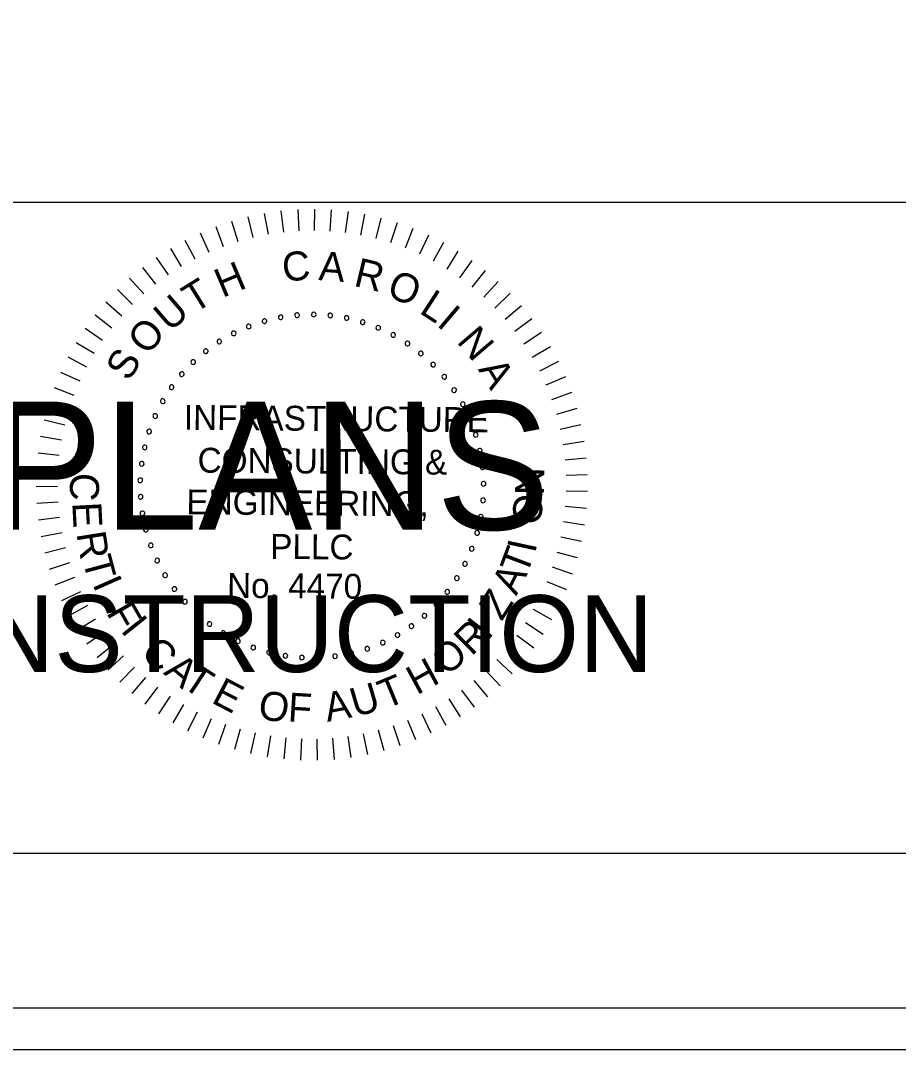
# Model space of a CAD drawing. Extents: x 967 to 1326, y 964 to 3144.
# Drawn here: x 1189.3 to 1212.88, y 2923.72 to 2951.36 of the extents above; entities that cross this region are included whole.
import ezdxf

# ---------------------------------------------------------------- set-up
doc = ezdxf.new("R2010")
doc.units = 0
for name, color, linetype in [('RD_SHT_Bndy', 7, 'Continuous'), ('RD_SHT_IplotShp', 7, 'Continuous'), ('RD_SHT_Misc1', 7, 'Continuous'), ('RD_SHT_Misc2', 7, 'Continuous'), ('RD_Sketch1', 7, 'Continuous')]:
    doc.layers.add(name, color=color, linetype=linetype)

msp = doc.modelspace()

# ---------------------------------------------------------------- linework, layer by layer
at = {"layer": 'RD_SHT_Bndy'}
for p, q in [((996.114, 2946.486), (1323.886, 2946.486)), ((1323.886, 2928.983), (996.114, 2928.983))]:
    msp.add_line(p, q, dxfattribs=at)
at = {"layer": 'RD_SHT_IplotShp'}
for points in [[(967.409, 2923.72), (1326.285, 2923.72), (1326.285, 3143.72), (967.409, 3143.72)], [(988.525, 2924.84), (1326.285, 2924.84), (1326.285, 3142.6), (988.525, 3142.6)]]:
    msp.add_lwpolyline(points, close=True, dxfattribs=at)
at = {"layer": 'RD_SHT_Misc1'}
for p, q in [((1195.846, 2946.181), (1195.945, 2945.62)), ((1196.292, 2946.245), (1196.357, 2945.68)), ((1196.742, 2946.282), (1196.772, 2945.714)), ((1197.194, 2946.292), (1197.189, 2945.723)), ((1197.645, 2946.274), (1197.606, 2945.706)), ((1198.094, 2946.228), (1198.02, 2945.664)), ((1198.54, 2946.156), (1198.432, 2945.596)), ((1194.968, 2945.971), (1195.134, 2945.427)), ((1195.403, 2946.09), (1195.536, 2945.536)), ((1198.98, 2946.056), (1198.838, 2945.504)), ((1199.414, 2945.929), (1199.238, 2945.387)), ((1194.122, 2945.656), (1194.353, 2945.136)), ((1194.54, 2945.827), (1194.739, 2945.293)), ((1199.839, 2945.777), (1199.63, 2945.246)), ((1200.253, 2945.598), (1200.013, 2945.082)), ((1193.715, 2945.461), (1193.978, 2944.956)), ((1200.656, 2945.395), (1200.385, 2944.894)), ((1193.321, 2945.241), (1193.614, 2944.752)), ((1201.047, 2945.167), (1200.745, 2944.684)), ((1192.94, 2944.997), (1193.263, 2944.528)), ((1201.422, 2944.917), (1201.092, 2944.453)), ((1192.576, 2944.731), (1192.926, 2944.282)), ((1201.781, 2944.643), (1201.424, 2944.2)), ((1192.228, 2944.443), (1192.605, 2944.016)), ((1202.124, 2944.349), (1201.739, 2943.928)), ((1191.899, 2944.134), (1192.301, 2943.731)), ((1202.447, 2944.034), (1202.038, 2943.638)), ((1191.589, 2943.805), (1192.015, 2943.428)), ((1202.751, 2943.7), (1202.318, 2943.329)), ((1191.299, 2943.459), (1191.748, 2943.108)), ((1191.032, 2943.095), (1191.501, 2942.772)), ((1203.034, 2943.348), (1202.579, 2943.004)), ((1203.294, 2942.979), (1202.82, 2942.664)), ((1190.787, 2942.716), (1191.274, 2942.422)), ((1203.532, 2942.595), (1203.04, 2942.31)), ((1190.565, 2942.323), (1191.07, 2942.059)), ((1203.746, 2942.198), (1203.237, 2941.943)), ((1190.368, 2941.916), (1190.888, 2941.684)), ((1203.936, 2941.788), (1203.412, 2941.564)), ((1190.196, 2941.499), (1190.729, 2941.299)), ((1204.1, 2941.367), (1203.563, 2941.176)), ((1190.05, 2941.072), (1190.594, 2940.905)), ((1204.238, 2940.937), (1203.691, 2940.779)), ((1189.93, 2940.636), (1190.484, 2940.503)), ((1204.349, 2940.5), (1203.794, 2940.375)), ((1189.837, 2940.195), (1190.398, 2940.095)), ((1204.434, 2940.056), (1203.872, 2939.966)), ((1189.771, 2939.748), (1190.337, 2939.683)), ((1204.491, 2939.608), (1203.925, 2939.552)), ((1189.732, 2939.298), (1190.301, 2939.267)), ((1204.522, 2939.158), (1203.953, 2939.137)), ((1189.721, 2938.847), (1190.29, 2938.851)), ((1204.524, 2938.706), (1203.955, 2938.72)), ((1189.737, 2938.396), (1190.306, 2938.434)), ((1204.499, 2938.256), (1203.932, 2938.304)), ((1189.781, 2937.946), (1190.346, 2938.019)), ((1204.447, 2937.807), (1203.884, 2937.89)), ((1189.852, 2937.5), (1190.412, 2937.608)), ((1204.367, 2937.363), (1203.81, 2937.479)), ((1189.951, 2937.06), (1190.502, 2937.201)), ((1204.261, 2936.924), (1203.712, 2937.074)), ((1190.076, 2936.626), (1190.617, 2936.8)), ((1204.128, 2936.492), (1203.589, 2936.676)), ((1190.227, 2936.2), (1190.757, 2936.408)), ((1203.969, 2936.07), (1203.442, 2936.286)), ((1190.403, 2935.785), (1190.92, 2936.024)), ((1203.784, 2935.658), (1203.271, 2935.906)), ((1190.605, 2935.381), (1191.106, 2935.651)), ((1203.574, 2935.258), (1203.078, 2935.537)), ((1190.831, 2934.99), (1191.315, 2935.291)), ((1203.341, 2934.871), (1202.862, 2935.18)), ((1191.081, 2934.614), (1191.545, 2934.943)), ((1203.085, 2934.5), (1202.626, 2934.837)), ((1191.353, 2934.253), (1191.796, 2934.61)), ((1191.646, 2933.91), (1192.067, 2934.293)), ((1202.806, 2934.145), (1202.368, 2934.509)), ((1191.96, 2933.585), (1192.356, 2933.994)), ((1202.506, 2933.807), (1202.092, 2934.197)), ((1192.293, 2933.28), (1192.664, 2933.712)), ((1202.186, 2933.488), (1201.796, 2933.903)), ((1192.644, 2932.996), (1192.988, 2933.45)), ((1201.847, 2933.19), (1201.484, 2933.628)), ((1193.011, 2932.734), (1193.327, 2933.208)), ((1201.119, 2932.657), (1200.811, 2933.136)), ((1201.491, 2932.912), (1201.155, 2933.372)), ((1193.394, 2932.495), (1193.68, 2932.987)), ((1200.731, 2932.425), (1200.453, 2932.922)), ((1193.791, 2932.279), (1194.047, 2932.788)), ((1194.2, 2932.088), (1194.424, 2932.612)), ((1200.331, 2932.217), (1200.083, 2932.73)), ((1194.62, 2931.923), (1194.812, 2932.459)), ((1195.05, 2931.783), (1195.208, 2932.33)), ((1199.495, 2931.877), (1199.312, 2932.416)), ((1199.918, 2932.034), (1199.702, 2932.561)), ((1195.487, 2931.67), (1195.612, 2932.225)), ((1195.93, 2931.584), (1196.021, 2932.146)), ((1196.377, 2931.524), (1196.434, 2932.091)), ((1196.828, 2931.493), (1196.85, 2932.062)), ((1197.279, 2931.488), (1197.267, 2932.058)), ((1197.73, 2931.512), (1197.683, 2932.079)), ((1198.179, 2931.562), (1198.097, 2932.126)), ((1198.624, 2931.64), (1198.508, 2932.198)), ((1199.063, 2931.745), (1198.913, 2932.295))]:
    msp.add_line(p, q, dxfattribs=at)
for centre, start, end in [((1196.285, 2943.388), 10.6038, 190.6038), ((1196.285, 2943.388), 190.6038, 10.6038), ((1196.727, 2943.447), 5.0653, 185.0653), ((1196.727, 2943.447), 185.0653, 5.0653), ((1197.172, 2943.464), 359.5268, 179.5268), ((1197.172, 2943.464), 179.5268, 359.5268), ((1197.617, 2943.438), 173.9884, 353.9884), ((1197.617, 2943.438), 353.9884, 173.9884), ((1198.057, 2943.369), 168.4499, 348.4499), ((1198.057, 2943.369), 348.4499, 168.4499), ((1195.429, 2943.142), 21.6807, 201.6807), ((1195.429, 2943.142), 201.6807, 21.6807), ((1195.851, 2943.285), 16.1422, 196.1422), ((1195.851, 2943.285), 196.1422, 16.1422), ((1198.489, 2943.258), 162.9114, 342.9114), ((1198.489, 2943.258), 342.9114, 162.9114), ((1198.908, 2943.106), 157.373, 337.373), ((1198.908, 2943.106), 337.373, 157.373), ((1195.023, 2942.958), 27.2191, 207.2191), ((1195.023, 2942.958), 207.2191, 27.2191), ((1199.31, 2942.914), 151.8345, 331.8345), ((1199.31, 2942.914), 331.8345, 151.8345), ((1194.274, 2942.478), 38.2961, 218.2961), ((1194.637, 2942.736), 32.7576, 212.7576), ((1194.637, 2942.736), 212.7576, 32.7576), ((1199.692, 2942.684), 146.2961, 326.2961), ((1199.692, 2942.684), 326.2961, 146.2961), ((1194.274, 2942.478), 218.2961, 38.2961), ((1200.05, 2942.419), 140.7576, 320.7576), ((1200.05, 2942.419), 320.7576, 140.7576), ((1193.937, 2942.186), 43.8345, 223.8345), ((1193.937, 2942.186), 223.8345, 43.8345), ((1200.38, 2942.12), 135.2191, 315.2191), ((1200.38, 2942.12), 315.2191, 135.2191), ((1193.63, 2941.862), 49.373, 229.373), ((1193.63, 2941.862), 229.373, 49.373), ((1200.68, 2941.79), 129.6807, 309.6807), ((1200.68, 2941.79), 309.6807, 129.6807), ((1193.356, 2941.511), 54.9114, 234.9114), ((1193.356, 2941.511), 234.9114, 54.9114), ((1200.947, 2941.433), 124.1422, 304.1422), ((1200.947, 2941.433), 304.1422, 124.1422), ((1193.117, 2941.135), 60.4499, 240.4499), ((1193.117, 2941.135), 240.4499, 60.4499), ((1201.179, 2941.052), 118.6038, 298.6038), ((1201.179, 2941.052), 298.6038, 118.6038), ((1192.915, 2940.737), 65.9884, 245.9884), ((1192.915, 2940.737), 245.9884, 65.9884), ((1201.372, 2940.651), 113.0653, 293.0653), ((1201.372, 2940.651), 293.0653, 113.0653), ((1192.753, 2940.322), 71.5268, 251.5268), ((1192.753, 2940.322), 251.5268, 71.5268), ((1201.526, 2940.233), 107.5268, 287.5268), ((1201.526, 2940.233), 287.5268, 107.5268), ((1192.632, 2939.894), 77.0653, 257.0653), ((1192.632, 2939.894), 257.0653, 77.0653), ((1201.638, 2939.801), 101.9884, 281.9884), ((1201.638, 2939.801), 281.9884, 101.9884), ((1192.552, 2939.455), 82.6038, 262.6038), ((1192.552, 2939.455), 262.6038, 82.6038), ((1201.709, 2939.361), 96.4499, 276.4499), ((1201.709, 2939.361), 276.4499, 96.4499), ((1192.515, 2939.011), 88.1422, 268.1422), ((1192.515, 2939.011), 268.1422, 88.1422), ((1201.737, 2938.917), 90.9114, 270.9114), ((1201.737, 2938.917), 270.9114, 90.9114), ((1192.522, 2938.565), 93.6807, 273.6807), ((1192.522, 2938.565), 273.6807, 93.6807), ((1201.721, 2938.471), 85.373, 265.373), ((1201.721, 2938.471), 265.373, 85.373), ((1192.571, 2938.122), 99.2191, 279.2191), ((1192.571, 2938.122), 279.2191, 99.2191), ((1201.663, 2938.029), 79.8345, 259.8345), ((1201.663, 2938.029), 259.8345, 79.8345), ((1192.662, 2937.686), 104.7576, 284.7576), ((1192.662, 2937.686), 284.7576, 104.7576), ((1201.563, 2937.595), 74.2961, 254.2961), ((1201.563, 2937.595), 254.2961, 74.2961), ((1192.796, 2937.261), 110.2961, 290.2961), ((1192.796, 2937.261), 290.2961, 110.2961), ((1201.42, 2937.173), 68.7576, 248.7576), ((1201.42, 2937.173), 248.7576, 68.7576), ((1192.97, 2936.851), 115.8345, 295.8345), ((1192.97, 2936.851), 295.8345, 115.8345), ((1201.238, 2936.766), 63.2191, 243.2191), ((1201.238, 2936.766), 243.2191, 63.2191), ((1193.182, 2936.459), 121.373, 301.373), ((1193.182, 2936.459), 301.373, 121.373), ((1201.018, 2936.379), 57.6807, 237.6807), ((1201.018, 2936.379), 237.6807, 57.6807), ((1193.432, 2936.09), 126.9114, 306.9114), ((1193.432, 2936.09), 306.9114, 126.9114), ((1200.761, 2936.014), 52.1422, 232.1422), ((1200.761, 2936.014), 232.1422, 52.1422), ((1193.715, 2935.746), 132.4499, 312.4499), ((1193.715, 2935.746), 312.4499, 132.4499), ((1200.47, 2935.677), 46.6038, 226.6038), ((1200.47, 2935.677), 226.6038, 46.6038), ((1194.031, 2935.431), 137.9884, 317.9884), ((1194.031, 2935.431), 317.9884, 137.9884), ((1200.148, 2935.369), 41.0653, 221.0653), ((1200.148, 2935.369), 221.0653, 41.0653), ((1194.376, 2935.149), 143.5268, 323.5268), ((1194.376, 2935.149), 323.5268, 143.5268), ((1199.798, 2935.093), 35.5268, 215.5268), ((1199.798, 2935.093), 215.5268, 35.5268), ((1194.746, 2934.901), 149.0653, 329.0653), ((1194.746, 2934.901), 329.0653, 149.0653), ((1199.422, 2934.853), 29.9884, 209.9884), ((1199.422, 2934.853), 209.9884, 29.9884), ((1195.139, 2934.69), 154.6038, 334.6038), ((1195.139, 2934.69), 334.6038, 154.6038), ((1195.55, 2934.517), 160.1422, 340.1422), ((1195.55, 2934.517), 340.1422, 160.1422), ((1198.611, 2934.486), 18.9114, 198.9114), ((1199.026, 2934.65), 24.4499, 204.4499), ((1199.026, 2934.65), 204.4499, 24.4499), ((1195.975, 2934.386), 165.6807, 345.6807), ((1195.975, 2934.386), 345.6807, 165.6807), ((1196.412, 2934.295), 171.2191, 351.2191), ((1196.412, 2934.295), 351.2191, 171.2191), ((1196.855, 2934.248), 356.7576, 176.7576), ((1196.855, 2934.248), 176.7576, 356.7576), ((1197.301, 2934.243), 2.2961, 182.2961), ((1197.301, 2934.243), 182.2961, 2.2961), ((1197.745, 2934.282), 7.8345, 187.8345), ((1197.745, 2934.282), 187.8345, 7.8345), ((1198.183, 2934.363), 13.373, 193.373), ((1198.183, 2934.363), 193.373, 13.373), ((1198.611, 2934.486), 198.9114, 18.9114)]:
    msp.add_arc(centre, 0.0627, start, end, dxfattribs=at)
at = {"layer": 'RD_Sketch1'}
msp.add_lwpolyline([(967.409, 2923.72), (1326.285, 2923.72), (1326.285, 3143.72), (967.409, 3143.72)], close=True, dxfattribs=at)

# ---------------------------------------------------------------- texts
at = {"layer": 'RD_SHT_Misc1'}
for s, height, rotation, p in [('C', 0.78, 4.7281, (1196.355, 2944.346)), ('A', 0.78, 355.6981, (1197.29, 2944.39)), ('H', 0.78, 22.7882, (1194.72, 2943.904)), ('R', 0.78, 346.6681, (1198.222, 2944.238)), ('T', 0.78, 31.8182, (1193.961, 2943.478)), ('O', 0.78, 337.638, (1199.096, 2943.972)), ('U', 0.78, 40.8482, (1193.306, 2942.976)), ('L', 0.78, 327.108, (1199.981, 2943.52)), ('I', 0.78, 319.578, (1200.451, 2943.182)), ('O', 0.78, 49.8782, (1192.707, 2942.341)), ('N', 0.78, 310.548, (1200.994, 2942.728)), ('S', 0.78, 58.9083, (1192.211, 2941.642)), ('A', 0.78, 301.5179, (1201.576, 2941.991)), ('INFRASTRUCTURE', 0.66873, 359.5268, (1193.682, 2940.367)), ('CONSULTING &', 0.66873, 359.5268, (1194.051, 2939.217)), ('N', 0.78, 89.2085, (1203.359, 2938.604)), ('C', 0.78, 267.025, (1190.646, 2939.227)), ('ENGINEERING,', 0.66873, 359.5268, (1193.751, 2938.095)), ('O', 0.78, 83.2085, (1203.26, 2937.786)), ('E', 0.78, 273.025, (1190.685, 2938.408)), ('R', 0.78, 279.025, (1190.799, 2937.583)), ('PLLC', 0.6687, 359.5268, (1196.002, 2936.9)), ('I', 0.78, 77.9093, (1203.121, 2937.032)), ('T', 0.78, 285.025, (1190.955, 2936.878)), ('T', 0.78, 69.3954, (1202.891, 2936.428)), ('I', 0.78, 293.7713, (1191.221, 2936.225)), ('No. 4470', 0.6687, 359.5268, (1194.843, 2935.855)), ('A', 0.78, 63.3954, (1202.616, 2935.888)), ('Z', 0.78, 57.3954, (1202.224, 2935.206)), ('F', 0.78, 299.7713, (1191.589, 2935.455)), ('I', 0.78, 308.5268, (1191.965, 2934.973)), ('R', 0.78, 44.5268, (1201.415, 2934.267)), ('I', 0.78, 52.3339, (1201.856, 2934.69)), ('C', 0.78, 314.5268, (1192.496, 2934.346)), ('O', 0.78, 38.5268, (1200.73, 2933.731)), ('A', 0.78, 320.5268, (1193.115, 2933.822)), ('T', 0.78, 326.5268, (1193.602, 2933.478)), ('H', 0.78, 28.5268, (1199.942, 2933.23)), ('E', 0.78, 332.5268, (1194.394, 2933.051)), ('T', 0.78, 22.5268, (1199.108, 2932.856)), ('U', 0.78, 16.5268, (1198.288, 2932.638)), ('O', 0.78, 350.5268, (1195.647, 2932.614)), ('F', 0.78, 356.5268, (1196.465, 2932.532)), ('A', 0.78, 10.5268, (1197.537, 2932.517))]:
    msp.add_text(s, height=height, rotation=rotation, dxfattribs=at).set_placement(p)
at = {"layer": 'RD_SHT_Misc2'}
for s, height, p in [('FINAL PLANS', 3.4375, (1174.145, 2937.685)), ('NOT FOR CONSTRUCTION', 2.0625, (1170.901, 2933.86))]:
    msp.add_text(s, height=height, dxfattribs=at).set_placement(p)

doc.saveas('drawing.dxf')
